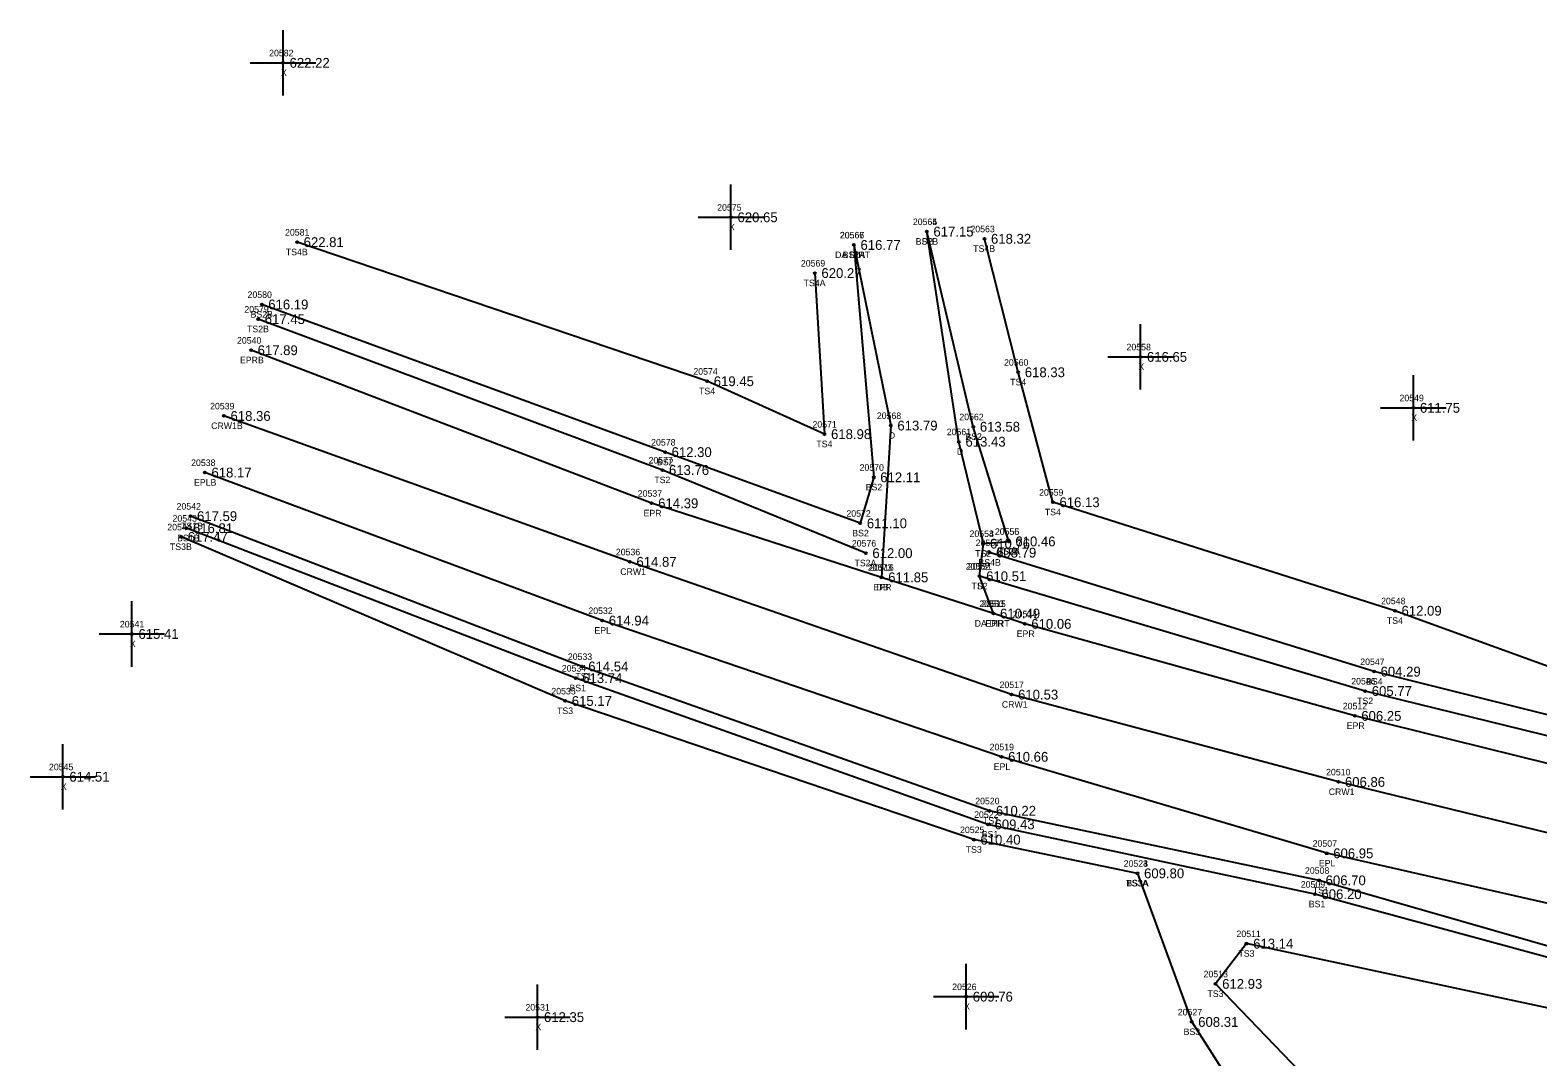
# Model space of a CAD drawing. Extents: x 1530159 to 1531652, y 877045 to 877724.
# Drawn here: x 1530158.5 to 1530389, y 877274.6 to 877431.6 of the extents above; entities that cross this region are included whole.
import ezdxf

# ---------------------------------------------------------------- set-up
doc = ezdxf.new("R2010")
doc.units = 0
for name, color, linetype in [('RD_DTM_BkLn1', 7, 'Continuous'), ('RD_DTM_BkLn2', 7, 'Continuous'), ('RD_DTM_BkLn_txCode', 7, 'Continuous'), ('RD_EX_Driveway', 7, 'Continuous'), ('RD_EX_Driveway_txCode', 7, 'Continuous'), ('RD_EX_Misc', 7, 'Continuous'), ('RD_EX_Misc_txCode', 7, 'Continuous'), ('RD_EX_Road', 7, 'Continuous'), ('RD_EX_Road_txCode', 7, 'Continuous'), ('RD_EX_TX_Driveway_ELEV', 7, 'Continuous'), ('RD_EX_TX_Misc_ELEV', 7, 'Continuous'), ('RD_EX_TX_Road_ELEV', 7, 'Continuous'), ('RD_HC_Survey_ELEV', 7, 'Continuous'), ('RD_HC_Survey_txCode', 7, 'Continuous'), ('RD_SMD_Locator', 7, 'Continuous')]:
    doc.layers.add(name, color=color, linetype=linetype)

msp = doc.modelspace()

# ---------------------------------------------------------------- linework, layer by layer
at = {"layer": 'RD_DTM_BkLn1'}
msp.add_lwpolyline([(1530865.56, 877271.01), (1530814.96, 877268.2), (1530763.15, 877267.89), (1530711.13, 877268.14), (1530659.67, 877269.22), (1530608.85, 877271.65), (1530559.07, 877277.33), (1530509.18, 877284.07), (1530458.44, 877292.62), (1530408.04, 877304.59), (1530358.54, 877316.67), (1530308.57, 877330.02), (1530250.23, 877350.32), (1530188.17, 877372.62)], dxfattribs=at)
at = {"layer": 'RD_DTM_BkLn2'}
for points in [[(1530284.48, 877398.76), (1530287.5, 877363.24), (1530285.45, 877356.21), (1530255.6, 877367.09), (1530193.94, 877389.66)], [(1530278.51, 877394.46), (1530279.98, 877369.84), (1530262.05, 877377.93), (1530199.35, 877399.19)], [(1530308.16, 877353.44), (1530302.73, 877370.97), (1530295.63, 877400.8)], [(1530472.87, 877358.33), (1530483.63, 877343.62), (1530471.95, 877322.92), (1530465.17, 877313.54), (1530412.95, 877326.2), (1530367.19, 877342.84), (1530314.9, 877359.43), (1530309.6, 877379.3), (1530304.43, 877399.7)], [(1530286.3, 877351.65), (1530255.2, 877364.35), (1530193.41, 877387.42)], [(1530846.55, 877195.51), (1530836.44, 877218.02), (1530825.43, 877234.54), (1530809.73, 877254.08), (1530787.3, 877254.89), (1530761.32, 877254.01), (1530707.75, 877254.4), (1530659.82, 877254.09), (1530608.22, 877255.41), (1530556.36, 877261.96), (1530505.86, 877268.16), (1530455.53, 877277.54), (1530404.07, 877287.69), (1530355.59, 877301.63), (1530305.18, 877312.26), (1530242.86, 877334.32), (1530183.05, 877357.3)], [(1530843.03, 877194.57), (1530830.04, 877216.97), (1530814.8, 877230.65), (1530802.93, 877234.88), (1530787.62, 877244.18), (1530761.15, 877248.01), (1530710.15, 877249.2), (1530659.29, 877248.38), (1530607.91, 877252.81), (1530555.6, 877260.07), (1530504.64, 877266.43), (1530454.3, 877275.47), (1530403.13, 877286.43), (1530354.95, 877299.51), (1530304.97, 877310.18), (1530241.94, 877332.54), (1530182.43, 877355.46)], [(1530327.83, 877302.7), (1530302.82, 877307.85), (1530240.34, 877329.05), (1530181.63, 877354.13)], [(1530780.69, 877332.06), (1530788.09, 877307.32), (1530788.66, 877295.54), (1530766.14, 877289.81), (1530711.07, 877289.67), (1530661.26, 877292.24), (1530608.81, 877294.06), (1530562.73, 877296.61), (1530511.3, 877298), (1530460.71, 877306.98), (1530411.43, 877318.55), (1530362.64, 877330.57), (1530303.69, 877348.12), (1530304.27, 877353.11), (1530308.16, 877353.44)], [(1530561.08, 877300.19), (1530512.66, 877301.03), (1530467.98, 877309.44), (1530461.57, 877310.81), (1530411.91, 877321.59), (1530363.99, 877333.54), (1530305.21, 877351.73)], [(1530327.83, 877302.7), (1530336.11, 877279.98), (1530350.95, 877256.76)], [(1530781.59, 877237.74), (1530769.19, 877234.54), (1530707.91, 877235.08), (1530658.9, 877217.43), (1530601.44, 877222.78), (1530585.47, 877250.74), (1530554.71, 877252.85), (1530502.71, 877258.91), (1530451.66, 877269.63), (1530401.38, 877279.82), (1530344.51, 877291.95), (1530339.77, 877285.8), (1530357.81, 877267.08), (1530377.75, 877244.03)]]:
    msp.add_lwpolyline(points, dxfattribs=at)
at = {"layer": 'RD_EX_Driveway'}
for points in [[(1530284.48, 877398.76), (1530290.12, 877371.15), (1530288.71, 877347.95)], [(1530305.81, 877342.41), (1530303.69, 877348.12), (1530304.27, 877353.11), (1530300.53, 877368.68), (1530295.63, 877400.8)]]:
    msp.add_lwpolyline(points, dxfattribs=at)
at = {"layer": 'RD_EX_Misc'}
for p, q in [((1530197.2, 877421.6), (1530197.2, 877431.6)), ((1530192.2, 877426.6), (1530202.2, 877426.6)), ((1530265.68, 877397.99), (1530265.68, 877407.99)), ((1530260.68, 877402.99), (1530270.68, 877402.99)), ((1530328.27, 877376.65), (1530328.27, 877386.65)), ((1530323.27, 877381.65), (1530333.27, 877381.65)), ((1530370, 877368.86), (1530370, 877378.86)), ((1530365, 877373.86), (1530375, 877373.86)), ((1530174.1, 877334.29), (1530174.1, 877344.29)), ((1530169.1, 877339.29), (1530179.1, 877339.29)), ((1530163.54, 877312.46), (1530163.54, 877322.46)), ((1530158.54, 877317.46), (1530168.54, 877317.46)), ((1530301.64, 877278.85), (1530301.64, 877288.85)), ((1530236.09, 877275.72), (1530236.09, 877285.72)), ((1530296.64, 877283.85), (1530306.64, 877283.85)), ((1530231.09, 877280.72), (1530241.09, 877280.72))]:
    msp.add_line(p, q, dxfattribs=at)
at = {"layer": 'RD_EX_Road'}
for points in [[(1530865.35, 877283.66), (1530865.36, 877280.61), (1530815.01, 877277.89), (1530763.54, 877277.33), (1530711.24, 877277.01), (1530660.64, 877277.93), (1530609.51, 877281.74), (1530559.88, 877286.96), (1530511.03, 877294.4), (1530460.35, 877303.35), (1530410.49, 877314.53), (1530361.04, 877326.77), (1530310.59, 877340.83), (1530305.81, 877342.41), (1530288.71, 877347.95), (1530253.55, 877359.27), (1530192.32, 877382.67)], [(1530866.41, 877261.44), (1530852.87, 877260.97), (1530806.23, 877259.4), (1530762.44, 877259.05), (1530711.8, 877259.77), (1530659.89, 877260.87), (1530608.32, 877263.5), (1530557.85, 877268.33), (1530507.29, 877275.71), (1530456.72, 877284.51), (1530406.3, 877294.52), (1530356.75, 877305.76), (1530307.05, 877320.51), (1530246, 877341.34), (1530185.26, 877363.97)]]:
    msp.add_lwpolyline(points, dxfattribs=at)
at = {"layer": 'RD_SMD_Locator'}
for centre in [(1530197.2, 877426.6), (1530265.68, 877402.99), (1530295.63, 877400.8), (1530295.63, 877400.8), (1530199.35, 877399.19), (1530284.48, 877398.76), (1530284.48, 877398.76), (1530304.43, 877399.7), (1530278.51, 877394.46), (1530193.94, 877389.66), (1530193.41, 877387.42), (1530192.32, 877382.67), (1530328.27, 877381.65), (1530262.05, 877377.93), (1530309.6, 877379.3), (1530370, 877373.86), (1530188.17, 877372.62), (1530290.12, 877371.15), (1530302.73, 877370.97), (1530279.98, 877369.84), (1530300.53, 877368.68), (1530255.6, 877367.09), (1530185.26, 877363.97), (1530255.2, 877364.35), (1530287.5, 877363.24), (1530314.9, 877359.43), (1530183.05, 877357.3), (1530253.55, 877359.27), (1530182.43, 877355.46), (1530285.45, 877356.21), (1530181.63, 877354.13), (1530304.27, 877353.11), (1530304.27, 877353.11), (1530308.16, 877353.44), (1530308.16, 877353.44), (1530250.23, 877350.32), (1530286.3, 877351.65), (1530305.21, 877351.73), (1530288.71, 877347.95), (1530288.71, 877347.95), (1530303.69, 877348.12), (1530303.69, 877348.12), (1530246, 877341.34), (1530305.81, 877342.41), (1530305.81, 877342.41), (1530367.19, 877342.84), (1530174.1, 877339.29), (1530310.59, 877340.83), (1530242.86, 877334.32), (1530241.94, 877332.54), (1530363.99, 877333.54), (1530308.57, 877330.02), (1530362.64, 877330.57), (1530240.34, 877329.05), (1530361.04, 877326.77), (1530307.05, 877320.51), (1530163.54, 877317.46), (1530358.54, 877316.67), (1530305.18, 877312.26), (1530304.97, 877310.18), (1530302.82, 877307.85), (1530356.75, 877305.76), (1530327.83, 877302.7), (1530327.83, 877302.7), (1530354.95, 877299.51), (1530355.59, 877301.63), (1530344.51, 877291.95), (1530339.77, 877285.8), (1530301.64, 877283.85), (1530236.09, 877280.72), (1530336.11, 877279.98)]:
    msp.add_circle(centre, 0.15, dxfattribs=at)

# ---------------------------------------------------------------- texts
at = {"layer": 'RD_DTM_BkLn_txCode'}
for s, p in [('20581', (1530197.51, 877400.19)), ('20564', (1530293.49, 877401.8)), ('20563', (1530302.29, 877400.7)), ('20567', (1530282.34, 877399.76)), ('BS2B', (1530293.93, 877398.8)), ('TS4B', (1530302.71, 877397.7)), ('TS4B', (1530197.63, 877397.19)), ('20569', (1530276.37, 877395.46)), ('BS2A', (1530282.77, 877396.76)), ('TS4A', (1530276.78, 877392.46)), ('20579', (1530191.29, 877388.42)), ('20580', (1530191.78, 877390.66)), ('BS2B', (1530192.24, 877387.66)), ('TS2B', (1530191.7, 877385.42)), ('20560', (1530307.42, 877380.3)), ('20574', (1530259.93, 877378.93)), ('TS4', (1530308.36, 877377.3)), ('TS4', (1530260.8, 877375.93)), ('20571', (1530278.14, 877370.84)), ('20562', (1530300.59, 877371.97)), ('20578', (1530253.48, 877368.09)), ('TS4', (1530278.73, 877367.84)), ('BS2', (1530301.5, 877368.97)), ('20577', (1530253.08, 877365.35)), ('BS2', (1530254.37, 877365.09)), ('20570', (1530285.34, 877364.24)), ('TS2', (1530253.96, 877362.35)), ('BS2', (1530286.27, 877361.24)), ('20559', (1530312.78, 877360.43)), ('20543', (1530180.31, 877356.46)), ('20542', (1530180.93, 877358.3)), ('20572', (1530283.33, 877357.21)), ('TS4', (1530313.66, 877357.43)), ('20544', (1530179.51, 877355.13)), ('TS1B', (1530181.62, 877355.3)), ('BS2', (1530284.22, 877354.21)), ('20554', (1530302.15, 877354.11)), ('20556', (1530306.02, 877354.44)), ('20555', (1530306.04, 877354.44)), ('TS3B', (1530179.91, 877352.13)), ('BS1B', (1530181.01, 877353.46)), ('20576', (1530284.16, 877352.65)), ('20557', (1530303.09, 877352.73)), ('TS2A', (1530284.56, 877349.65)), ('TS2', (1530303.02, 877351.11)), ('BS4B', (1530303.51, 877349.73)), ('TS2B', (1530306.44, 877351.44)), ('BS2A', (1530306.44, 877351.44)), ('20552', (1530301.57, 877349.12)), ('TS2', (1530302.45, 877346.12)), ('20548', (1530365.07, 877343.84)), ('TS4', (1530365.95, 877340.84)), ('20534', (1530239.82, 877333.54)), ('20533', (1530240.74, 877335.32)), ('20547', (1530361.88, 877334.54)), ('TS1', (1530241.9, 877332.32)), ('20546', (1530360.5, 877331.57)), ('BS4', (1530362.77, 877331.54)), ('20535', (1530238.22, 877330.05)), ('BS1', (1530240.99, 877330.54)), ('TS2', (1530361.4, 877328.57)), ('TS3', (1530239.09, 877327.05)), ('20520', (1530303.02, 877313.26)), ('20522', (1530302.85, 877311.18)), ('TS1', (1530304.22, 877310.26)), ('20525', (1530300.7, 877308.85)), ('BS1', (1530304.02, 877308.18)), ('TS3', (1530301.57, 877305.85)), ('20523', (1530325.71, 877303.7)), ('20524', (1530325.71, 877303.7)), ('20508', (1530353.43, 877302.63)), ('TS3A', (1530326.1, 877300.7)), ('BS3A', (1530326.12, 877300.7)), ('20509', (1530352.79, 877300.51)), ('TS1', (1530354.63, 877299.63)), ('BS1', (1530354.01, 877297.51)), ('20511', (1530342.96, 877292.95)), ('TS3', (1530343.26, 877289.95)), ('20513', (1530337.93, 877286.8)), ('TS3', (1530338.52, 877283.8)), ('20527', (1530333.99, 877280.98)), ('BS3', (1530334.88, 877277.98))]:
    msp.add_text(s, height=1, dxfattribs=at).set_placement(p)
at = {"layer": 'RD_EX_Driveway_txCode'}
for s, p in [('20565', (1530293.49, 877401.8)), ('20566', (1530282.32, 877399.76)), ('DB', (1530294.85, 877398.8)), ('DA DIRT', (1530281.6, 877396.76)), ('20568', (1530287.98, 877372.15)), ('D', (1530289.81, 877369.15)), ('20561', (1530298.67, 877369.68)), ('D', (1530300.22, 877366.68)), ('20553', (1530302.15, 877354.11)), ('D', (1530303.96, 877351.11)), ('20573', (1530286.59, 877348.95)), ('20551', (1530301.86, 877349.12)), ('DB', (1530287.93, 877345.95)), ('D', (1530303.38, 877346.12)), ('20550', (1530303.65, 877343.41)), ('DA DIRT', (1530302.93, 877340.41))]:
    msp.add_text(s, height=1, dxfattribs=at).set_placement(p)
at = {"layer": 'RD_EX_Misc_txCode'}
for s, p in [('20582', (1530195.08, 877427.6)), ('X', (1530196.89, 877424.6)), ('20575', (1530263.57, 877403.99)), ('X', (1530265.37, 877400.99)), ('20558', (1530326.15, 877382.65)), ('X', (1530327.96, 877379.65)), ('20549', (1530367.88, 877374.86)), ('X', (1530369.68, 877371.86)), ('20541', (1530172.26, 877340.29)), ('X', (1530173.78, 877337.29)), ('20545', (1530161.42, 877318.46)), ('X', (1530163.23, 877315.46)), ('20526', (1530299.5, 877284.85)), ('20531', (1530234.26, 877281.72)), ('X', (1530301.33, 877281.85)), ('X', (1530235.78, 877278.72))]:
    msp.add_text(s, height=1, dxfattribs=at).set_placement(p)
at = {"layer": 'RD_EX_Road_txCode'}
for s, p in [('20540', (1530190.17, 877383.67)), ('EPRB', (1530190.62, 877380.67)), ('20538', (1530183.15, 877364.97)), ('EPLB', (1530183.59, 877361.97)), ('20537', (1530251.43, 877360.27)), ('EPR', (1530252.32, 877357.27)), ('20516', (1530286.85, 877348.95)), ('EPR', (1530287.48, 877345.95)), ('20532', (1530243.88, 877342.34)), ('20515', (1530303.97, 877343.41)), ('EPR', (1530304.58, 877340.41)), ('20514', (1530308.76, 877341.83)), ('EPL', (1530244.8, 877339.34)), ('EPR', (1530309.36, 877338.83)), ('20512', (1530359.21, 877327.77)), ('EPR', (1530359.82, 877324.77)), ('20519', (1530305.22, 877321.51)), ('EPL', (1530305.85, 877318.51)), ('20507', (1530354.6, 877306.76)), ('EPL', (1530355.55, 877303.76))]:
    msp.add_text(s, height=1, dxfattribs=at).set_placement(p)
at = {"layer": 'RD_EX_TX_Driveway_ELEV'}
for s, p in [('617.15', (1530296.63, 877400.05)), ('616.77', (1530285.48, 877398.01)), ('613.79', (1530291.12, 877370.4)), ('613.43', (1530301.53, 877367.93)), ('610.76', (1530305.27, 877352.36)), ('611.85', (1530289.71, 877347.2)), ('610.51', (1530304.69, 877347.37)), ('610.49', (1530306.81, 877341.66))]:
    msp.add_text(s, height=1.5, dxfattribs=at).set_placement(p)
at = {"layer": 'RD_EX_TX_Misc_ELEV'}
for s, p in [('622.22', (1530198.2, 877425.85)), ('620.65', (1530266.68, 877402.24)), ('617.15', (1530296.63, 877400.05)), ('622.81', (1530200.35, 877398.44)), ('616.77', (1530285.48, 877398.01)), ('618.32', (1530305.43, 877398.95)), ('620.27', (1530279.51, 877393.71)), ('616.19', (1530194.94, 877388.91)), ('617.45', (1530194.41, 877386.67)), ('616.65', (1530329.27, 877380.9)), ('619.45', (1530263.05, 877377.18)), ('618.33', (1530310.6, 877378.55)), ('611.75', (1530371, 877373.11)), ('613.58', (1530303.73, 877370.22)), ('618.98', (1530280.98, 877369.09)), ('612.30', (1530256.6, 877366.34)), ('613.76', (1530256.2, 877363.6)), ('612.11', (1530288.5, 877362.49)), ('616.13', (1530315.9, 877358.68)), ('617.59', (1530184.05, 877356.55)), ('617.47', (1530182.63, 877353.38)), ('616.81', (1530183.43, 877354.71)), ('611.10', (1530286.45, 877355.46)), ('610.76', (1530305.27, 877352.36)), ('610.46', (1530309.16, 877352.69)), ('610.46', (1530309.16, 877352.69)), ('612.00', (1530287.3, 877350.9)), ('608.79', (1530306.21, 877350.98)), ('610.51', (1530304.69, 877347.37)), ('612.09', (1530368.19, 877342.09)), ('615.41', (1530175.1, 877338.54)), ('614.54', (1530243.86, 877333.57)), ('604.29', (1530364.99, 877332.79)), ('613.74', (1530242.94, 877331.79)), ('615.17', (1530241.34, 877328.3)), ('605.77', (1530363.64, 877329.82)), ('614.51', (1530164.54, 877316.71)), ('610.22', (1530306.18, 877311.51)), ('609.43', (1530305.97, 877309.43)), ('610.40', (1530303.82, 877307.1)), ('609.80', (1530328.83, 877301.95)), ('609.80', (1530328.83, 877301.95)), ('606.70', (1530356.59, 877300.88)), ('606.20', (1530355.95, 877298.76)), ('613.14', (1530345.51, 877291.2)), ('612.93', (1530340.77, 877285.05)), ('609.76', (1530302.64, 877283.1)), ('612.35', (1530237.09, 877279.97)), ('608.31', (1530337.11, 877279.23))]:
    msp.add_text(s, height=1.5, dxfattribs=at).set_placement(p)
at = {"layer": 'RD_EX_TX_Road_ELEV'}
for s, p in [('617.89', (1530193.32, 877381.92)), ('618.17', (1530186.26, 877363.22)), ('614.39', (1530254.55, 877358.52)), ('611.85', (1530289.71, 877347.2)), ('614.94', (1530247, 877340.59)), ('610.49', (1530306.81, 877341.66)), ('610.06', (1530311.59, 877340.08)), ('606.25', (1530362.04, 877326.02)), ('610.66', (1530308.05, 877319.76)), ('606.95', (1530357.75, 877305.01))]:
    msp.add_text(s, height=1.5, dxfattribs=at).set_placement(p)
at = {"layer": 'RD_HC_Survey_ELEV'}
for s, p in [('618.36', (1530189.17, 877371.87)), ('614.87', (1530251.23, 877349.57)), ('610.53', (1530309.57, 877329.27)), ('606.86', (1530359.54, 877315.92))]:
    msp.add_text(s, height=1.5, dxfattribs=at).set_placement(p)
at = {"layer": 'RD_HC_Survey_txCode'}
for s, p in [('20539', (1530186.05, 877373.62)), ('CRW1B', (1530186.21, 877370.62)), ('20536', (1530248.08, 877351.32)), ('CRW1', (1530248.75, 877348.32)), ('20517', (1530306.74, 877331.02)), ('CRW1', (1530307.09, 877328.02)), ('20510', (1530356.66, 877317.67)), ('CRW1', (1530357.06, 877314.67))]:
    msp.add_text(s, height=1, dxfattribs=at).set_placement(p)

doc.saveas('drawing.dxf')
